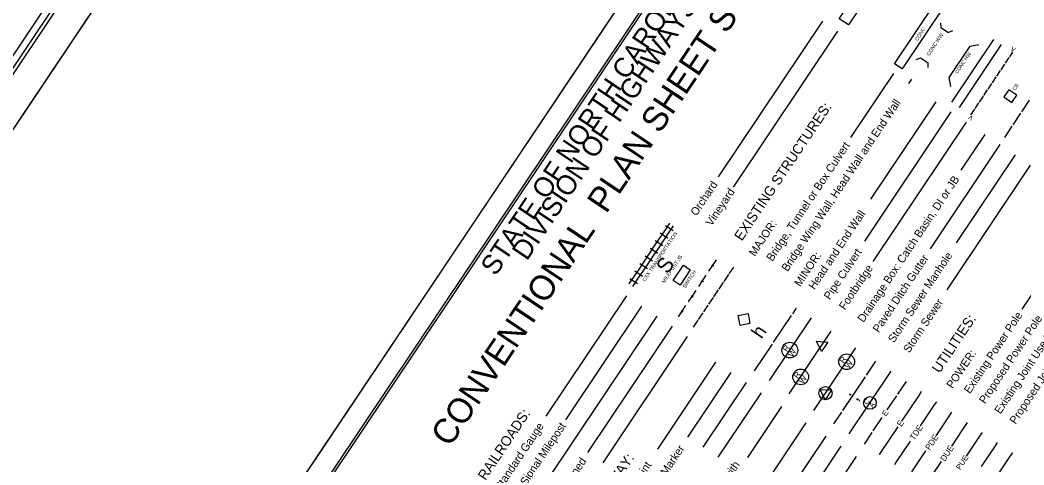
# Model space of a CAD drawing. Extents: x 1715610 to 1720914, y 798298 to 802505.
# Drawn here: x 1717939 to 1719036, y 799960 to 800447 of the extents above; entities that cross this region are included whole.
import ezdxf

# ---------------------------------------------------------------- set-up
doc = ezdxf.new("R2010")
doc.units = 0
for name, color, linetype in [('Prop Easement Permanent Drainage Utility', 7, 'Continuous'), ('Prop Shade Medium', 7, 'Continuous'), ('Sheet Cutting Line CELL', 7, 'Continuous'), ('Sheet Plot Border Inside CELL', 7, 'Continuous'), ('Sheet Plot Border Outside CELL', 7, 'Continuous'), ('Sheet Symbology CELL', 7, 'Continuous'), ('Sheet Title CELL', 7, 'Continuous')]:
    doc.layers.add(name, color=color, linetype=linetype)

msp = doc.modelspace()

# ---------------------------------------------------------------- linework, layer by layer
at = {"layer": 'Prop Easement Permanent Drainage Utility'}
for p, q in [((1718957.3, 799980.8), (1718974.6, 800006.7)), ((1718928.8, 799938.1), (1718946.2, 799964.1))]:
    msp.add_line(p, q, dxfattribs=at)
at = {"layer": 'Prop Shade Medium'}
msp.add_lwpolyline([(1718725.9, 800112.8), (1718723.7, 800123.7), (1718734.6, 800125.8), (1718736.7, 800115)], close=True, dxfattribs=at)
at = {"layer": 'Sheet Cutting Line CELL'}
for p, q in [((1717369.7, 799488.2), (1718774.7, 801587.4)), ((1718932.4, 800968.7), (1717995.7, 799569.3))]:
    msp.add_line(p, q, dxfattribs=at)
at = {"layer": 'Sheet Plot Border Inside CELL'}
for points in [[(1717352.6, 799523.2), (1718743, 801600.5), (1717427.7, 802480.8), (1716037.3, 800403.5)], [(1718898.4, 798980.7), (1719825.4, 800365.7), (1718948.6, 800952.5), (1718021.6, 799567.6)]]:
    msp.add_lwpolyline(points, close=True, dxfattribs=at)
at = {"layer": 'Sheet Plot Border Outside CELL'}
for points in [[(1717403.5, 802505.2), (1715998.5, 800406), (1717369.7, 799488.2), (1718774.7, 801587.4)], [(1718909.9, 798957.4), (1719846.5, 800356.9), (1718932.4, 800968.7), (1717995.7, 799569.3)]]:
    msp.add_lwpolyline(points, close=True, dxfattribs=at)
at = {"layer": 'Sheet Symbology CELL'}
for p, q in [((1718815.9, 800445.5), (1718701.9, 800275.2)), ((1718945.2, 800443.5), (1718945.3, 800438.5)), ((1718832.5, 800434.4), (1718718.5, 800264)), ((1718945.3, 800438.5), (1718953.7, 800433)), ((1718958.3, 800434.8), (1718953.7, 800433)), ((1718957.5, 800356.7), (1719003.3, 800425.3)), ((1718954.4, 800383.6), (1718977.3, 800417.9)), ((1718965.8, 800351.1), (1719011.7, 800419.7)), ((1718977.3, 800417.9), (1718987.1, 800419.8)), ((1719020.8, 800406.4), (1719024.1, 800411.4)), ((1718918.4, 800403.5), (1718923.1, 800405.3)), ((1718923.1, 800405.3), (1718931.4, 800399.7)), ((1718931.5, 800394.7), (1718931.4, 800399.7)), ((1719016.1, 800399.3), (1719020.2, 800405.5)), ((1719006.6, 800385.2), (1719010.8, 800391.4)), ((1719011.3, 800392.3), (1719015.5, 800398.5)), ((1718893.6, 800388.2), (1718846.7, 800318.1)), ((1718910.3, 800377.1), (1718913.6, 800382.1)), ((1718956.3, 800373.8), (1718954.4, 800383.6)), ((1719001.9, 800378.1), (1719006, 800384.4)), ((1718992.4, 800364), (1718996.6, 800370.2)), ((1718997.1, 800371.1), (1719001.3, 800377.3)), ((1718939.8, 800357.3), (1718868.5, 800250.7)), ((1718983, 800349.9), (1718987.1, 800356.1)), ((1718987.7, 800356.9), (1718991.9, 800363.2)), ((1719034.1, 800346.3), (1719042.4, 800358.8)), ((1718956.4, 800346.2), (1718861.8, 800204.8)), ((1718978.2, 800342.8), (1718982.4, 800349)), ((1719024.6, 800332.2), (1719033, 800344.7)), ((1718973.1, 800335.1), (1718871, 800182.6)), ((1719015.2, 800318.1), (1719023.5, 800330.6)), ((1718993.4, 800321.5), (1718967.1, 800282.3)), ((1719010, 800310.4), (1718933.8, 800196.6)), ((1719026.6, 800299.2), (1718962.3, 800203.1)), ((1719043.2, 800288.1), (1718951.9, 800151.7)), ((1719111.3, 800245.9), (1719034.1, 800130.7)), ((1718643.6, 800216.3), (1718649.1, 800224.6)), ((1718638, 800207.9), (1718643.6, 800216.3)), ((1718647, 800207.9), (1718638.7, 800213.5)), ((1718642.2, 800205.2), (1718647.7, 800213.5)), ((1718652.6, 800216.2), (1718644.3, 800221.8)), ((1718647.7, 800213.5), (1718653.3, 800221.8)), ((1718632.4, 800199.6), (1718638, 800207.9)), ((1718641.5, 800199.6), (1718633.1, 800205.2)), ((1718636.6, 800196.9), (1718642.2, 800205.2)), ((1718621.3, 800183), (1718626.9, 800191.3)), ((1718626.9, 800191.3), (1718632.4, 800199.6)), ((1718635.9, 800191.3), (1718627.6, 800196.9)), ((1718631, 800188.5), (1718636.6, 800196.9)), ((1718615.8, 800174.7), (1718621.3, 800183)), ((1718624.8, 800174.7), (1718616.5, 800180.2)), ((1718619.9, 800171.9), (1718625.5, 800180.2)), ((1718630.3, 800183), (1718622, 800188.6)), ((1718625.5, 800180.2), (1718631, 800188.5)), ((1718691.8, 800171.9), (1718700.2, 800184.4)), ((1718610.2, 800166.4), (1718615.8, 800174.7)), ((1718619.2, 800166.4), (1718610.9, 800171.9)), ((1718614.3, 800163.6), (1718619.9, 800171.9)), ((1718695, 800178.9), (1718697, 800177.5)), ((1718714, 800169.1), (1718719, 800176.6)), ((1718604.6, 800158.1), (1718610.2, 800166.4)), ((1718613.6, 800158.1), (1718605.3, 800163.6)), ((1718608.8, 800155.3), (1718614.3, 800163.6)), ((1718680.7, 800155.3), (1718689, 800167.8)), ((1718683.8, 800162.2), (1718685.9, 800160.8)), ((1718702.9, 800152.5), (1718707.9, 800160)), ((1718708.4, 800160.8), (1718713.5, 800168.3)), ((1718669.6, 800138.7), (1718677.9, 800151.1)), ((1718697.3, 800144.2), (1718702.3, 800151.7)), ((1718601.7, 800145.1), (1718513.6, 800013.5)), ((1718672.7, 800145.6), (1718674.8, 800144.2)), ((1718691.8, 800135.9), (1718696.8, 800143.3)), ((1718618.3, 800134), (1718535.1, 800009.7)), ((1718658.5, 800122.1), (1718666.8, 800134.5)), ((1718661.6, 800129), (1718663.7, 800127.6)), ((1718680.6, 800119.2), (1718685.6, 800126.7)), ((1718686.2, 800127.6), (1718691.2, 800135)), ((1718783.5, 800125.6), (1718787.7, 800131.8)), ((1718634.9, 800122.9), (1718515.4, 799944.3)), ((1718675.1, 800110.9), (1718680.1, 800118.4)), ((1718758, 800052.4), (1718803.9, 800121)), ((1718762.6, 800094.5), (1718782.1, 800123.5)), ((1718651.6, 800111.8), (1718559.1, 799973.7)), ((1718779.7, 800037.9), (1718825.6, 800106.4)), ((1718668.2, 800100.6), (1718575.8, 799962.6)), ((1718668.2, 800100.6), (1718575.8, 799962.6)), ((1718741.8, 800063.3), (1718761.2, 800092.4)), ((1718806.7, 800019.8), (1718852.6, 800088.4)), ((1718815.6, 800091.4), (1718815.6, 800091.4)), ((1718699.1, 800072.5), (1718635.6, 799977.6)), ((1718864.1, 800058.3), (1718874.4, 800073.8)), ((1718715.7, 800061.4), (1718668.5, 799990.8)), ((1718845.2, 799994.1), (1718891.1, 800062.6)), ((1718732.4, 800050.3), (1718685.1, 799979.7)), ((1718838.3, 800019.7), (1718863, 800056.6)), ((1718898.4, 800037.6), (1718907.7, 800051.5)), ((1718749, 800039.2), (1718701.7, 799968.6)), ((1718819.4, 800038.7), (1718819.4, 800038.7)), ((1718921.6, 800036.3), (1718924.3, 800040.4)), ((1718886.8, 800020.4), (1718897.3, 800035.9)), ((1718902.8, 800008.3), (1718921.6, 800036.3)), ((1718938.6, 800025.8), (1718940.9, 800029.3)), ((1718771.3, 800024.2), (1718734, 799968.5)), ((1718828.5, 800005.2), (1718837.1, 800018.1)), ((1718923.3, 800003), (1718938.6, 800025.8)), ((1718955.5, 800015.1), (1718957.5, 800018.1)), ((1718797.9, 800006.4), (1718760.6, 799950.6)), ((1718871.5, 799997.5), (1718881.3, 800012.1)), ((1718940.2, 799992.2), (1718955.5, 800015.1)), ((1718861.8, 799983), (1718870.4, 799995.8)), ((1718879.9, 799974), (1718898.6, 800002.1)), ((1718988.7, 799992.8), (1718990.8, 799995.9)), ((1718819.6, 799991.9), (1718765.4, 799910.8)), ((1718896.9, 799963.5), (1718912.2, 799986.3)), ((1718973.5, 799970), (1718988.7, 799992.8)), ((1719005.1, 799981.3), (1719007.4, 799984.8)), ((1718836.2, 799980.8), (1718782, 799899.7)), ((1718878.4, 799971.8), (1718879.9, 799974)), ((1718913.8, 799952.7), (1718929.1, 799975.6)), ((1718989.8, 799958.5), (1719005.1, 799981.3)), ((1719021.7, 799970.2), (1719024, 799973.6)), ((1718852.9, 799969.6), (1718798.6, 799888.6)), ((1718895, 799960.7), (1718896.9, 799963.5)), ((1719006.4, 799947.3), (1719021.7, 799970.2))]:
    msp.add_line(p, q, dxfattribs=at)
for points in [[(1718943.7, 800940.7), (1718109.4, 799694.2), (1718981.1, 799110.7), (1719815.5, 800357.2)], [(1719023.2, 800356.5), (1719028.6, 800364.5), (1719019.7, 800370.4), (1719014.4, 800362.5)], [(1718652.7, 800162), (1718663.9, 800178.6), (1718671.4, 800173.5), (1718660.3, 800156.9)], [(1718815.1, 800084.2), (1718809.6, 800095.4), (1718822, 800094.6)], [(1718818.9, 800031.5), (1718813.4, 800042.7), (1718825.8, 800041.9)]]:
    msp.add_lwpolyline(points, close=True, dxfattribs=at)
for points in [[(1718834.4, 800448), (1718878.9, 800514.5), (1718888.9, 800507.8), (1718844.4, 800441.3), (1718834.4, 800448)], [(1718894.7, 800398.7), (1718940.5, 800467.3), (1718948.9, 800461.7), (1718903, 800393.2), (1718894.7, 800398.7)]]:
    msp.add_lwpolyline(points, dxfattribs=at)
for centre, radius in [((1718780.3, 800085.8), 8.61), ((1718842.4, 800073.1), 8.61), ((1718792.2, 800056.5), 8.61), ((1718819.4, 800038.7), 7.2), ((1718867.9, 800028.1), 6.89)]:
    msp.add_circle(centre, radius, dxfattribs=at)
at = {"layer": 'Sheet Title CELL'}
for points in [[(1717486.2, 799729.7), (1718721, 801574.6)], [(1717809.5, 800226.3), (1718126.6, 800700)]]:
    msp.add_lwpolyline(points, dxfattribs=at)

# ---------------------------------------------------------------- texts
at = {"layer": 'Prop Easement Permanent Drainage Utility'}
msp.add_text('DUE', height=6.55, rotation=56.2051, dxfattribs=at).set_placement((1718949.8, 799963.6))
at = {"layer": 'Sheet Symbology CELL'}
for s, height, rotation, p in [('CONVENTIONAL  PLAN SHEET SYMBOLS', 27.2, 56.2051, (1718408.7, 799978.7)), ('STATE OF NORTH CAROLINA', 21.419, 56.2051, (1718458.7, 800165.8)), ('DIVISION OF HIGHWAYS', 21.419, 56.2051, (1718492.9, 800182.5)), ('CONC', 4, 56.2051, (1718919.9, 800423.3)), ('CONC WW', 4, 56.2051, (1718932.7, 800407.1)), ('CONC HW', 4, 56.2051, (1718963.8, 800387.4)), ('v', 6.6, 326.4459, (1719021, 800413.4)), ('CB', 4, 56.2051, (1719026.6, 800369)), ('Bridge Wing Wall, Head Wall and End Wall', 8.75, 56.2051, (1718777.8, 800171)), ('EXISTING STRUCTURES:', 11, 56.2051, (1718727.9, 800204.4)), ('v', 6.6, 145.9642, (1718981.3, 800340.7)), ('Bridge, Tunnel or Box Culvert', 8.75, 56.2051, (1718761.2, 800182.1)), ('Orchard', 8.75, 56.2051, (1718678.3, 800231.7)), ('Drainage Box: Catch Basin, DI or JB', 8.75, 56.2051, (1718860.9, 800115.4)), ('Vineyard', 8.75, 56.2051, (1718694.9, 800220.6)), ('Head and End Wall', 8.75, 56.2051, (1718807.3, 800151.2)), ('MAJOR:', 8.75, 56.2051, (1718742.1, 800187.6)), ('CSX TRANSPORTATION', 4, 56.2051, (1718622.1, 800160.3)), ('MINOR:', 8.75, 56.2051, (1718791.7, 800154.4)), ('Pipe Culvert', 8.75, 56.2051, (1718824, 800140.1)), ('Storm Sewer Manhole', 8.75, 56.2051, (1718894.1, 800093.1)), ('S', 16.5, 56.2051, (1718646.7, 800168.1)), ('MILEPOST 35', 4, 56.2051, (1718643.2, 800158.5)), ('Paved Ditch Gutter', 8.75, 56.2051, (1718877.5, 800104.3)), ('SWITCH', 4, 56.2051, (1718666, 800153)), ('Footbridge', 8.75, 56.2051, (1718840.6, 800129)), ('Storm Sewer', 8.75, 56.2051, (1718910.8, 800082)), ('Existing Power Pole', 8.75, 56.2051, (1718977.2, 800037.5)), ('UTILITIES:', 11, 56.2051, (1718944, 800059.8)), ('Proposed Power Pole', 8.75, 56.2051, (1718993.8, 800026.4)), ('Existing Joint Use Pole', 8.75, 56.2051, (1719010.5, 800015.3)), ('Proposed Joint Use Pole', 8.75, 56.2051, (1719027.1, 800004.2)), ('h', 15, 56.2051, (1718749.5, 800097.3)), ('R', 6.75, 56.2051, (1718777.4, 800083.2)), ('W', 6.75, 56.2051, (1718783.2, 800077.5)), ('POWER:', 8.75, 56.2051, (1718958.1, 800043.1)), ('R', 6.75, 56.2051, (1718839.5, 800070.6)), ('W', 6.75, 56.2051, (1718845.2, 800064.9)), ('R', 6.75, 56.2051, (1718789.3, 800054)), ('W', 6.75, 56.2051, (1718795, 800048.3)), (';', 15, 56.2051, (1718853.5, 800029.1)), ('C', 5.4, 56.2051, (1718865.2, 800025.5)), ('A', 5.4, 56.2051, (1718870.9, 800022.3)), ('RAILROADS:', 11, 56.2051, (1718447.6, 799942.7)), ('E', 6, 56.2051, (1718885.5, 800013)), ('Standard Gauge', 8.75, 56.2051, (1718464.1, 799931.4)), ('RR Signal Milepost', 8.75, 56.2051, (1718480.7, 799920.3)), ('E', 6.55, 56.2051, (1718902.3, 800001.5)), ('TDE', 6.55, 56.2051, (1718916.4, 799986.7)), ('PDE', 6.55, 56.2051, (1718933.2, 799975.8)), ('RIGHT OF WAY:', 11, 56.2051, (1718548.5, 799875.2)), ('Existing Right of Way Marker', 8.75, 56.2051, (1718581.7, 799853)), ('RR Abandoned', 8.75, 56.2051, (1718513.9, 799898)), ('Baseline Control Point', 8.75, 56.2051, (1718565.1, 799864.1)), ('Proposed Right of Way Line with', 8.75, 56.2051, (1718631.6, 799819.6)), ('PUE', 6, 56.2051, (1718966.5, 799954.3))]:
    msp.add_text(s, height=height, rotation=rotation, dxfattribs=at).set_placement(p)

doc.saveas('drawing.dxf')
